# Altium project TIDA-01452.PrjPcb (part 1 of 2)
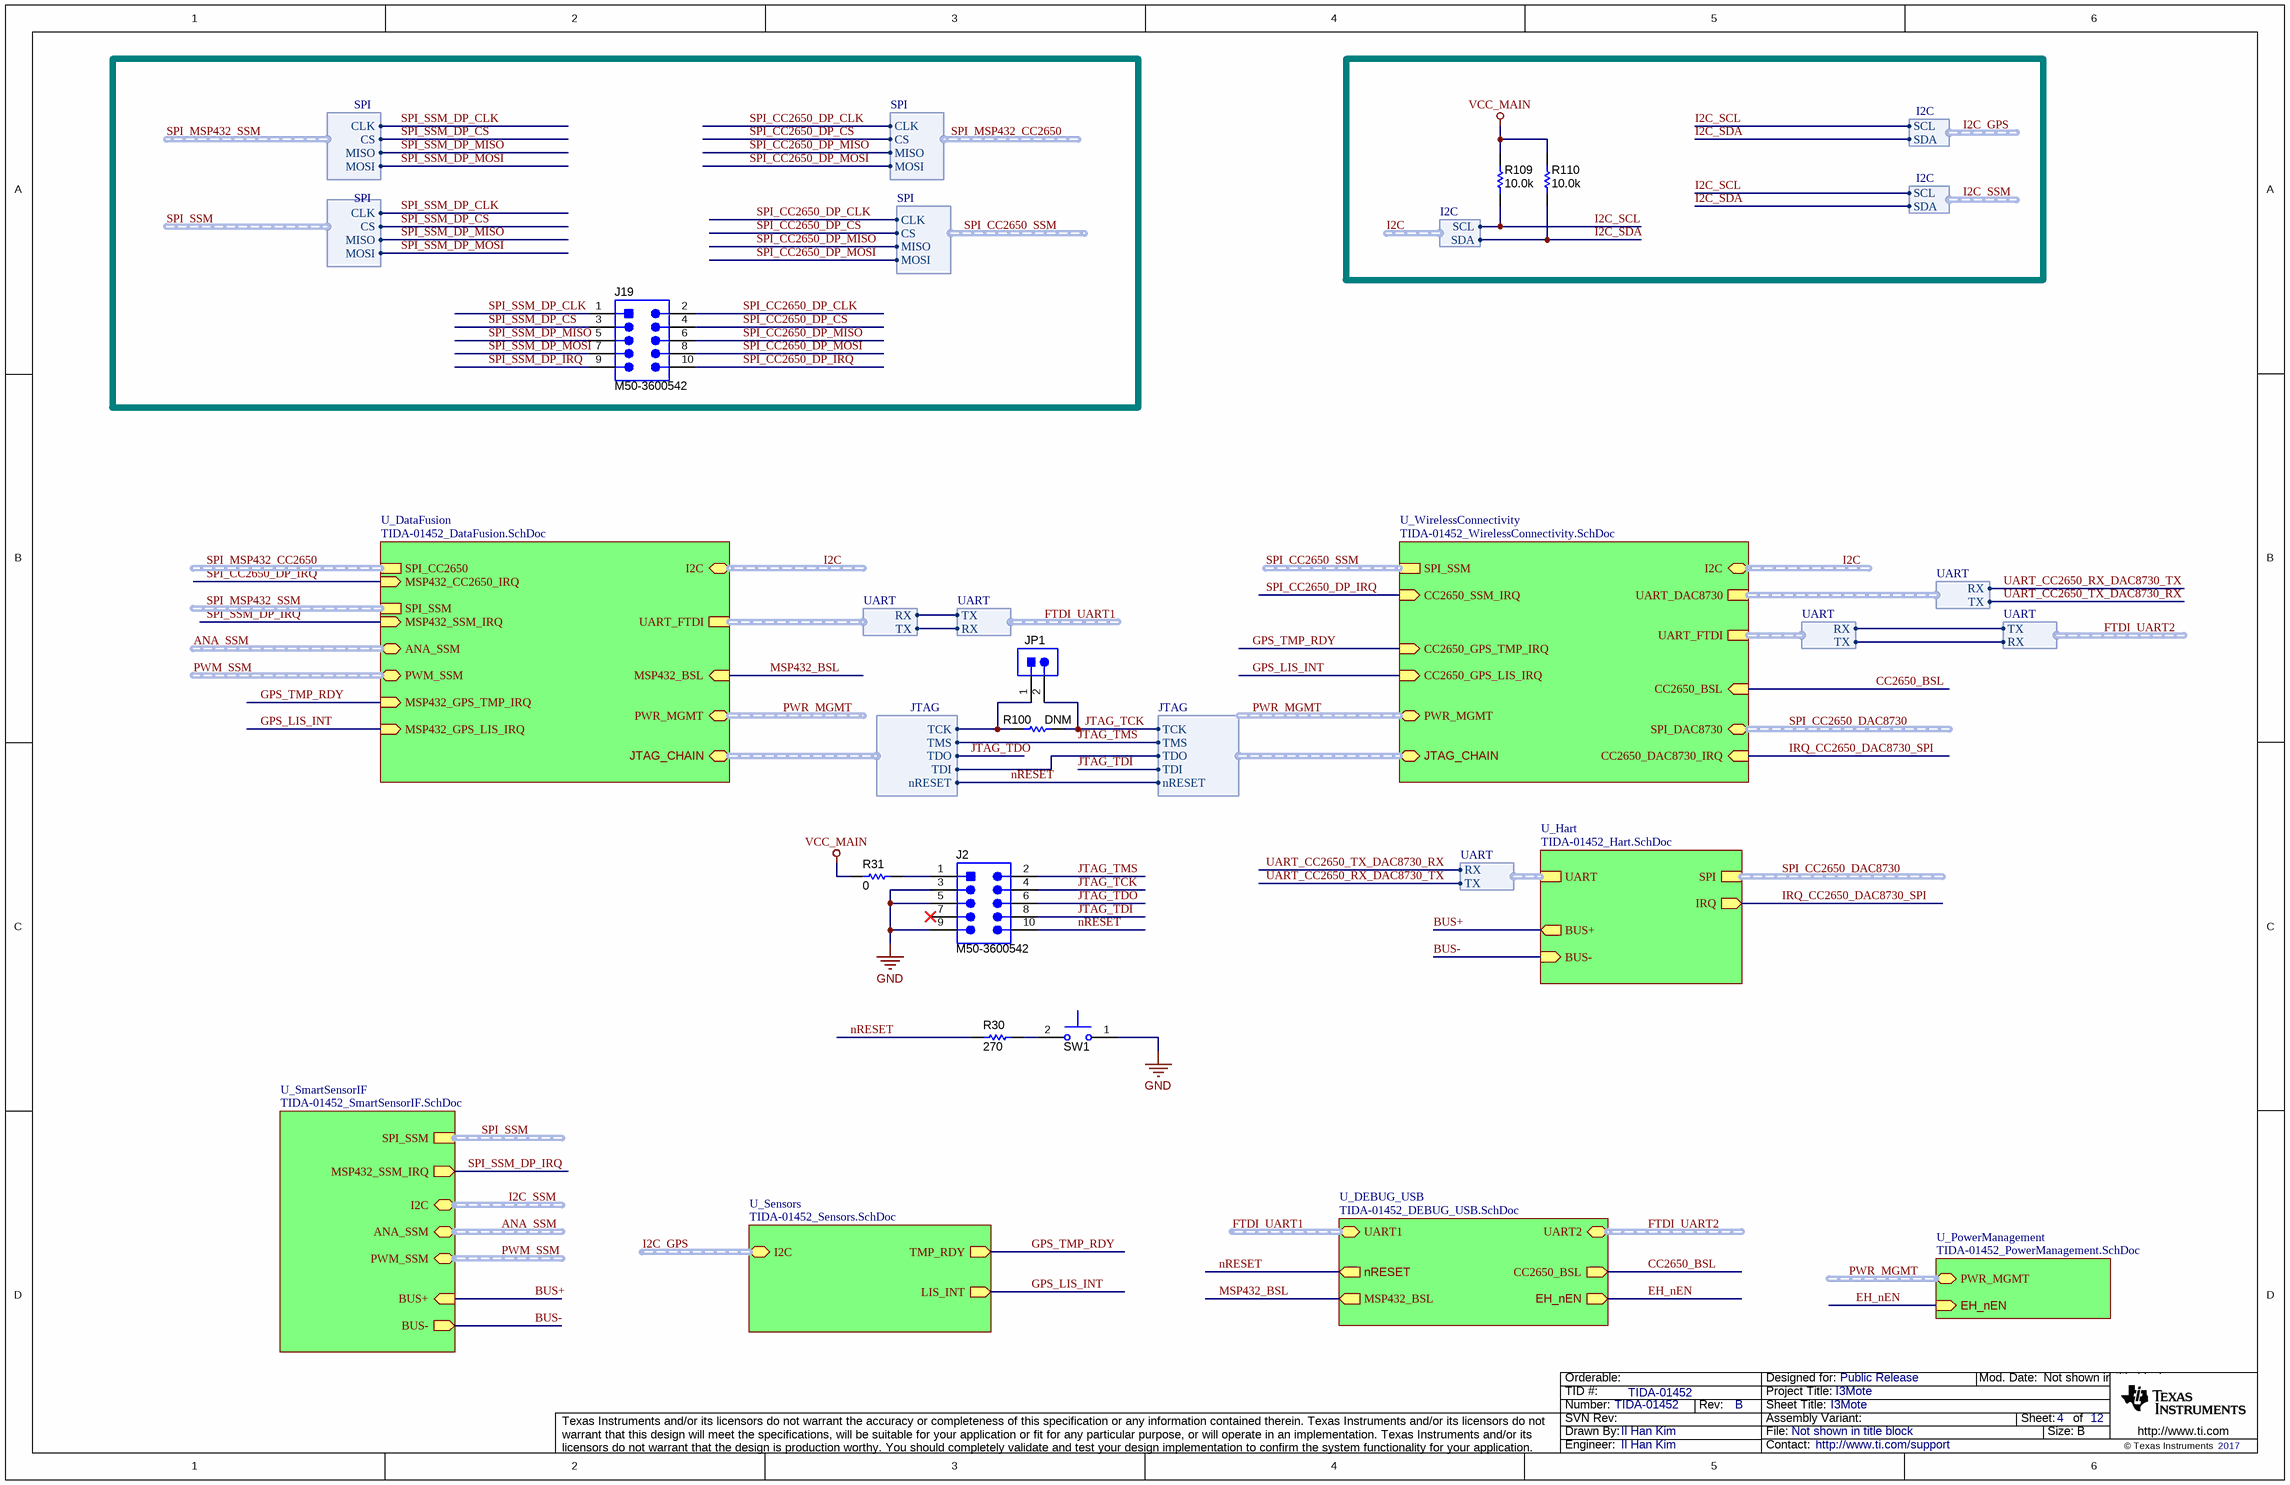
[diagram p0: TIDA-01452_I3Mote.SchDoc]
CopyrightYear: 2017; PCB_Layout: Il Han Kim; PCB_Rev: B; PRJ_Customer: Public Release; PRJ_Engineer: Il Han Kim; PRJ_Number: TIDA-01452; PRJ_Title: I3Mote; SCH_Rev: B; TechSupport: http://www.ti.com/support; TID: TIDA-01452
9 sheets, 257 parts. Net scope: hierarchical (ports join the sheet entries above them; power ports are global).
Board file: TIDA-01452.PcbDoc
Sheets:
  TIDA-01452_I3Mote.SchDoc
    U_Sensors = TIDA-01452_Sensors.SchDoc
    U_PowerManagement = TIDA-01452_PowerManagement.SchDoc
      U_PWR_EH = TIDA-01452_PWR_EH.SchDoc
    U_Hart = TIDA-01452_Hart.SchDoc
    U_DEBUG_USB = TIDA-01452_DEBUG_USB.SchDoc
    U_WirelessConnectivity = TIDA-01452_WirelessConnectivity.SchDoc
    U_DataFusion = TIDA-01452_DataFusion.SchDoc
    U_SmartSensorIF = TIDA-01452_SmartSensorIF.SchDoc

## Sheet TIDA-01452_I3Mote.SchDoc: I3Mote
size 431 x 279 mm; Date: Not shown in title block; ApprovedBy: Not shown in title block; CheckedBy: Not shown in title block; Author: Not shown in title block; CompanyName: Not shown in title block; DrawnBy: Il Han Kim; Engineer: Not shown in title block; Organization: Not shown in title block; Address1: Not shown in title block; Address2: Not shown in title block; Address3: Not shown in title block; Address4: Not shown in title block; DocumentNumber: 7; Revision: Use project parameter SCH_Rev; SheetNumber: 4; SheetTotal: 12; PageSetup: Record=PageOptions¦CenterHorizontal=True¦CenterVertical=True¦PrintScale=0.64¦XCorrection=1.00¦YCorrection=1.00¦PrintKind=0¦BorderSize=5000000¦LeftOffset=0¦BottomOffset=0¦Orientation=2¦PaperLength=1000¦PaperWidth=1000¦Scale=100¦PaperSource=15¦PrintQuality=600¦MediaType=1¦DitherType=10¦PrintScaleMode=1¦PaperKind=Letter

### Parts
J2  M50-3600542  [Harwin_M50-3600542]
J19  M50-3600542  [Harwin_M50-3600542]
JP1  TMM-102-01-T-S  [CONN_TMM-102-01-T-S]  (value not drawn)
R30  ValueDisplayed: 270  [0402]  (hidden comment: CRCW0402270RFKED)
R31  ValueDisplayed: 0  [0402]  (hidden comment: CRCW04020000Z0ED)
R100  DNM  [0402]
R109  ValueDisplayed: 10.0k  [0402]  (hidden comment: CRCW040210K0FKED)
R110  ValueDisplayed: 10.0k  [0402]  (hidden comment: CRCW040210K0FKED)
SW1  B3U-1000P  [SW_B3U-1000P]  (value not drawn)

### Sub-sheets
U_DataFusion = TIDA-01452_DataFusion.SchDoc: UART_FTDI (harness UART), SPI_SSM (harness SPI), SPI_CC2650 (harness SPI), MSP432_GPS_TMP_IRQ (in), MSP432_CC2650_IRQ (in), MSP432_BSL (in), PWR_MGMT (harness PWR_MGMT), MSP432_SSM_IRQ (in), PWM_SSM (harness PWM), ANA_SSM (harness ANA), I2C (harness I2C), JTAG_CHAIN (harness JTAG), MSP432_GPS_LIS_IRQ (in)
U_DEBUG_USB = TIDA-01452_DEBUG_USB.SchDoc: CC2650_BSL (out), MSP432_BSL (out), UART1 (harness UART), UART2 (harness UART), EH_nEN (out), nRESET (out)
U_Hart = TIDA-01452_Hart.SchDoc: SPI (harness SPI), UART (harness UART), IRQ (out), BUS- (in), BUS+ (out)
U_PowerManagement = TIDA-01452_PowerManagement.SchDoc: PWR_MGMT (harness PWR_MGMT), EH_nEN (in)
U_Sensors = TIDA-01452_Sensors.SchDoc: TMP_RDY (out), I2C (harness I2C), LIS_INT (out)
U_SmartSensorIF = TIDA-01452_SmartSensorIF.SchDoc: SPI_SSM (harness SPI), MSP432_SSM_IRQ (out), PWM_SSM (harness PWM), ANA_SSM (harness ANA), I2C (harness I2C), BUS- (out), BUS+ (in)
U_WirelessConnectivity = TIDA-01452_WirelessConnectivity.SchDoc: SPI_SSM (harness SPI), UART_DAC8730 (harness UART), UART_FTDI (harness UART), CC2650_SSM_IRQ (in), CC2650_GPS_TMP_IRQ (in), CC2650_BSL (in), PWR_MGMT (harness PWR_MGMT), CC2650_DAC8730_IRQ (in), SPI_DAC8730 (harness SPI), I2C (harness I2C), JTAG_CHAIN (harness JTAG), CC2650_GPS_LIS_IRQ (in)

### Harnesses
UART: RX, TX
I2C: SCL, SDA
SPI: CLK, CS, MISO, MOSI
JTAG: TMS, TCK, TDO, TDI, nRESET

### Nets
GND: J2.3 J2.5 J2.9 SW1.1
VCC_MAIN: R31.1 R109.1 R110.1
BUS+: sheet U_Hart/BUS+, sheet U_SmartSensorIF/BUS+
BUS-: sheet U_Hart/BUS-, sheet U_SmartSensorIF/BUS-
CC2650_BSL: sheet U_DEBUG_USB/CC2650_BSL, sheet U_WirelessConnectivity/CC2650_BSL
CC2650_FTDI_UART_RX: sheet U_WirelessConnectivity/UART_FTDI.RX, sheet U_DEBUG_USB/UART2.TX
CC2650_FTDI_UART_TX: sheet U_WirelessConnectivity/UART_FTDI.TX, sheet U_DEBUG_USB/UART2.RX
CC2650_JTAG_TDO: sheet U_DataFusion/JTAG_CHAIN.TDI, sheet U_WirelessConnectivity/JTAG_CHAIN.TDO
EH_nEN: sheet U_PowerManagement/EH_nEN, sheet U_DEBUG_USB/EH_nEN
FTDI_UART1.RX: sheet U_DataFusion/UART_FTDI.TX, sheet U_DEBUG_USB/UART1.RX
FTDI_UART1.TX: sheet U_DataFusion/UART_FTDI.RX, sheet U_DEBUG_USB/UART1.TX
GPS_LIS_INT: sheet U_Sensors/LIS_INT, sheet U_WirelessConnectivity/CC2650_GPS_LIS_IRQ, sheet U_DataFusion/MSP432_GPS_LIS_IRQ  [project net CC2650_GPS_LIS_IRQ]
GPS_TMP_RDY: sheet U_Sensors/TMP_RDY, sheet U_WirelessConnectivity/CC2650_GPS_TMP_IRQ, sheet U_DataFusion/MSP432_GPS_TMP_IRQ  [project net CC2650_GPS_TMP_IRQ]
I2C_SCL: R109.2 ; sheet U_WirelessConnectivity/I2C.SCL, sheet U_Sensors/I2C.SCL, sheet U_SmartSensorIF/I2C.SCL  [project net CC2650_GPS_I2C_SCL]
I2C_SDA: R110.2 ; sheet U_WirelessConnectivity/I2C.SDA, sheet U_Sensors/I2C.SDA, sheet U_SmartSensorIF/I2C.SDA  [project net CC2650_GPS_I2C_SDA]
IRQ_CC2650_DAC8730_SPI: sheet U_Hart/IRQ, sheet U_WirelessConnectivity/CC2650_DAC8730_IRQ  [project net CC2650_DAC8730_IRQ]
JTAG_TCK: J2.4 JP1.2 R100.2 ; sheet U_WirelessConnectivity/JTAG_CHAIN.TCK  [project net CC2650_JTAG_TCK]
JTAG_TDI: J2.8 ; sheet U_WirelessConnectivity/JTAG_CHAIN.TDI  [project net CC2650_JTAG_TDI]
JTAG_TDO: J2.6 ; sheet U_DataFusion/JTAG_CHAIN.TDO
JTAG_TMS: J2.2 ; sheet U_DataFusion/JTAG_CHAIN.TMS, sheet U_WirelessConnectivity/JTAG_CHAIN.TMS  [project net CC2650_JTAG_TMS]
MSP432_BSL: sheet U_DEBUG_USB/MSP432_BSL, sheet U_DataFusion/MSP432_BSL
MSP432_JTAG_TCK: JP1.1 R100.1 ; sheet U_DataFusion/JTAG_CHAIN.TCK
nRESET: J2.10 R30.1 ; sheet U_DEBUG_USB/nRESET, sheet U_DataFusion/JTAG_CHAIN.nRESET, sheet U_WirelessConnectivity/JTAG_CHAIN.nRESET  [project net CC2650_nRESET]
SPI_CC2650_DP_CLK: J19.2 ; sheet U_DataFusion/SPI_CC2650.CLK, sheet U_WirelessConnectivity/SPI_SSM.CLK  [project net CC2650_SSM_SPI_CLK]
SPI_CC2650_DP_CS: J19.4 ; sheet U_DataFusion/SPI_CC2650.CS, sheet U_WirelessConnectivity/SPI_SSM.CS  [project net CC2650_SSM_SPI_CS]
SPI_CC2650_DP_IRQ: J19.10 ; sheet U_WirelessConnectivity/CC2650_SSM_IRQ, sheet U_DataFusion/MSP432_CC2650_IRQ  [project net CC2650_SSM_IRQ]
SPI_CC2650_DP_MISO: J19.6 ; sheet U_DataFusion/SPI_CC2650.MISO, sheet U_WirelessConnectivity/SPI_SSM.MISO  [project net CC2650_SSM_SPI_MISO]
SPI_CC2650_DP_MOSI: J19.8 ; sheet U_DataFusion/SPI_CC2650.MOSI, sheet U_WirelessConnectivity/SPI_SSM.MOSI  [project net CC2650_SSM_SPI_MOSI]
SPI_SSM_DP_CLK: J19.1 ; sheet U_DataFusion/SPI_SSM.CLK, sheet U_SmartSensorIF/SPI_SSM.CLK  [project net MSP432_SSM_SPI_CLK]
SPI_SSM_DP_CS: J19.3 ; sheet U_DataFusion/SPI_SSM.CS, sheet U_SmartSensorIF/SPI_SSM.CS  [project net MSP432_SSM_SPI_CS]
SPI_SSM_DP_IRQ: J19.9 ; sheet U_DataFusion/MSP432_SSM_IRQ, sheet U_SmartSensorIF/MSP432_SSM_IRQ  [project net IRQ_MSP432_SSM]
SPI_SSM_DP_MISO: J19.5 ; sheet U_DataFusion/SPI_SSM.MISO, sheet U_SmartSensorIF/SPI_SSM.MISO  [project net MSP432_SSM_SPI_MISO]
SPI_SSM_DP_MOSI: J19.7 ; sheet U_DataFusion/SPI_SSM.MOSI, sheet U_SmartSensorIF/SPI_SSM.MOSI  [project net MSP432_SSM_SPI_MOSI]
UART_CC2650_RX_DAC8730_TX: sheet U_Hart/UART.TX, sheet U_WirelessConnectivity/UART_DAC8730.RX  [project net CC2650_DAC8730_UART_RX]
UART_CC2650_TX_DAC8730_RX: sheet U_Hart/UART.RX, sheet U_WirelessConnectivity/UART_DAC8730.TX  [project net CC2650_DAC8730_UART_TX]
NetJ2_1: J2.1 R31.2
NetR30_2: R30.2 SW1.2

Not connected (* = marked no-connect by the designer): J2 7*

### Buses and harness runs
harness ANA_SSM = sheet U_DataFusion/ANA_SSM
harness ANA_SSM = sheet U_SmartSensorIF/ANA_SSM
harness FTDI_UART1 = sheet U_DEBUG_USB/UART1
harness FTDI_UART2 = sheet U_DEBUG_USB/UART2
harness I2C = sheet U_DataFusion/I2C
harness I2C = sheet U_WirelessConnectivity/I2C
harness I2C_GPS = sheet U_Sensors/I2C
harness I2C_SSM = sheet U_SmartSensorIF/I2C
harness PWM_SSM = sheet U_DataFusion/PWM_SSM
harness PWM_SSM = sheet U_SmartSensorIF/PWM_SSM
harness PWR_MGMT = sheet U_DataFusion/PWR_MGMT
harness PWR_MGMT = sheet U_PowerManagement/PWR_MGMT
harness PWR_MGMT = sheet U_WirelessConnectivity/PWR_MGMT
harness SPI_CC2650_DAC8730 = sheet U_Hart/SPI
harness SPI_CC2650_DAC8730 = sheet U_WirelessConnectivity/SPI_DAC8730
harness SPI_CC2650_SSM = sheet U_WirelessConnectivity/SPI_SSM
harness SPI_MSP432_CC2650 = sheet U_DataFusion/SPI_CC2650
harness SPI_MSP432_SSM = sheet U_DataFusion/SPI_SSM
harness SPI_SSM = sheet U_SmartSensorIF/SPI_SSM

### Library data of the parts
J2 J19 = M50-3600542: Header, 1.27mm, 5x2, Gold, SMT; Manufacturer: Harwin; SymbolCreator: a0412235; Pitch_mm: 1.27; Gender: Male; Shrouded: N; Row_Count: 2; Current_A: 1; Voltage_V: 1000; Cert_UL: Y
JP1 = TMM-102-01-T-S: Header, 2mm, 2x1, Tin, TH; Manufacturer: Samtec; SymbolCreator: a0412235; U/M: EA
R30 = CRCW0402270RFKED: RES, 270, 1%, 0.0625W, 50V, 0402; Manufacturer: Vishay-Dale; Value: 270
R31 R100 = CRCW04020000Z0ED: RES, 0, 5%, 0.063 W, 0402; Manufacturer: Vishay-Dale; CompType: Resistor; Value: 0; Value_Code: 0000; Tolerance_%: 5; Power_W: 0.063; Value2: 0.063W; VDC_V: 50; TempCo: 200 ppm/C; EIA_Code: E24; U/M: EA
R109 R110 = CRCW040210K0FKED: RES, 10.0 k, 1%, 0.063 W, 0402; Manufacturer: Vishay-Dale; CompType: Resistor; Value: 10.0k; Res_ohm: 10000; Value_Code: 10k0; Tolerance_%: 1; Power_W: 0.063; Value2: 0.063W; VDC_V: 50; TempCo: 100 ppm/C; EIA_Code: E96; U/M: EA; AEC Category: Q200
SW1 = B3U-1000P: SWITCH TACTILE SPST-NO 0.05A 12V; Manufacturer: Omron Electronic Components; SymbolCreator: a0412235; VDC_V: 12; SwitchFunction: Off-Mom; PositionCount: 1; CurrentRating_mA: 50

## Sheet TIDA-01452_Sensors.SchDoc: Sensors
size 431 x 279 mm; Date: Not shown in title block; ApprovedBy: Not shown in title block; CheckedBy: Not shown in title block; Author: Not shown in title block; CompanyName: Not shown in title block; DrawnBy: Il Han Kim; Engineer: Not shown in title block; Organization: Not shown in title block; Address1: Not shown in title block; Address2: Not shown in title block; Address3: Not shown in title block; Address4: Not shown in title block; DocumentNumber: 10; Revision: Use project parameter SCH_Rev; SheetNumber: 6; SheetTotal: 12; PageSetup: Record=PageOptions¦CenterHorizontal=True¦CenterVertical=True¦PrintScale=1.00¦XCorrection=1.00¦YCorrection=1.00¦PrintKind=0¦BorderSize=5000000¦LeftOffset=0¦BottomOffset=0¦Orientation=2¦PaperLength=1000¦PaperWidth=1000¦Scale=100¦PaperSource=15¦PrintQuality=600¦MediaType=1¦DitherType=10¦PaperKind=Letter¦PrintScaleMode=1
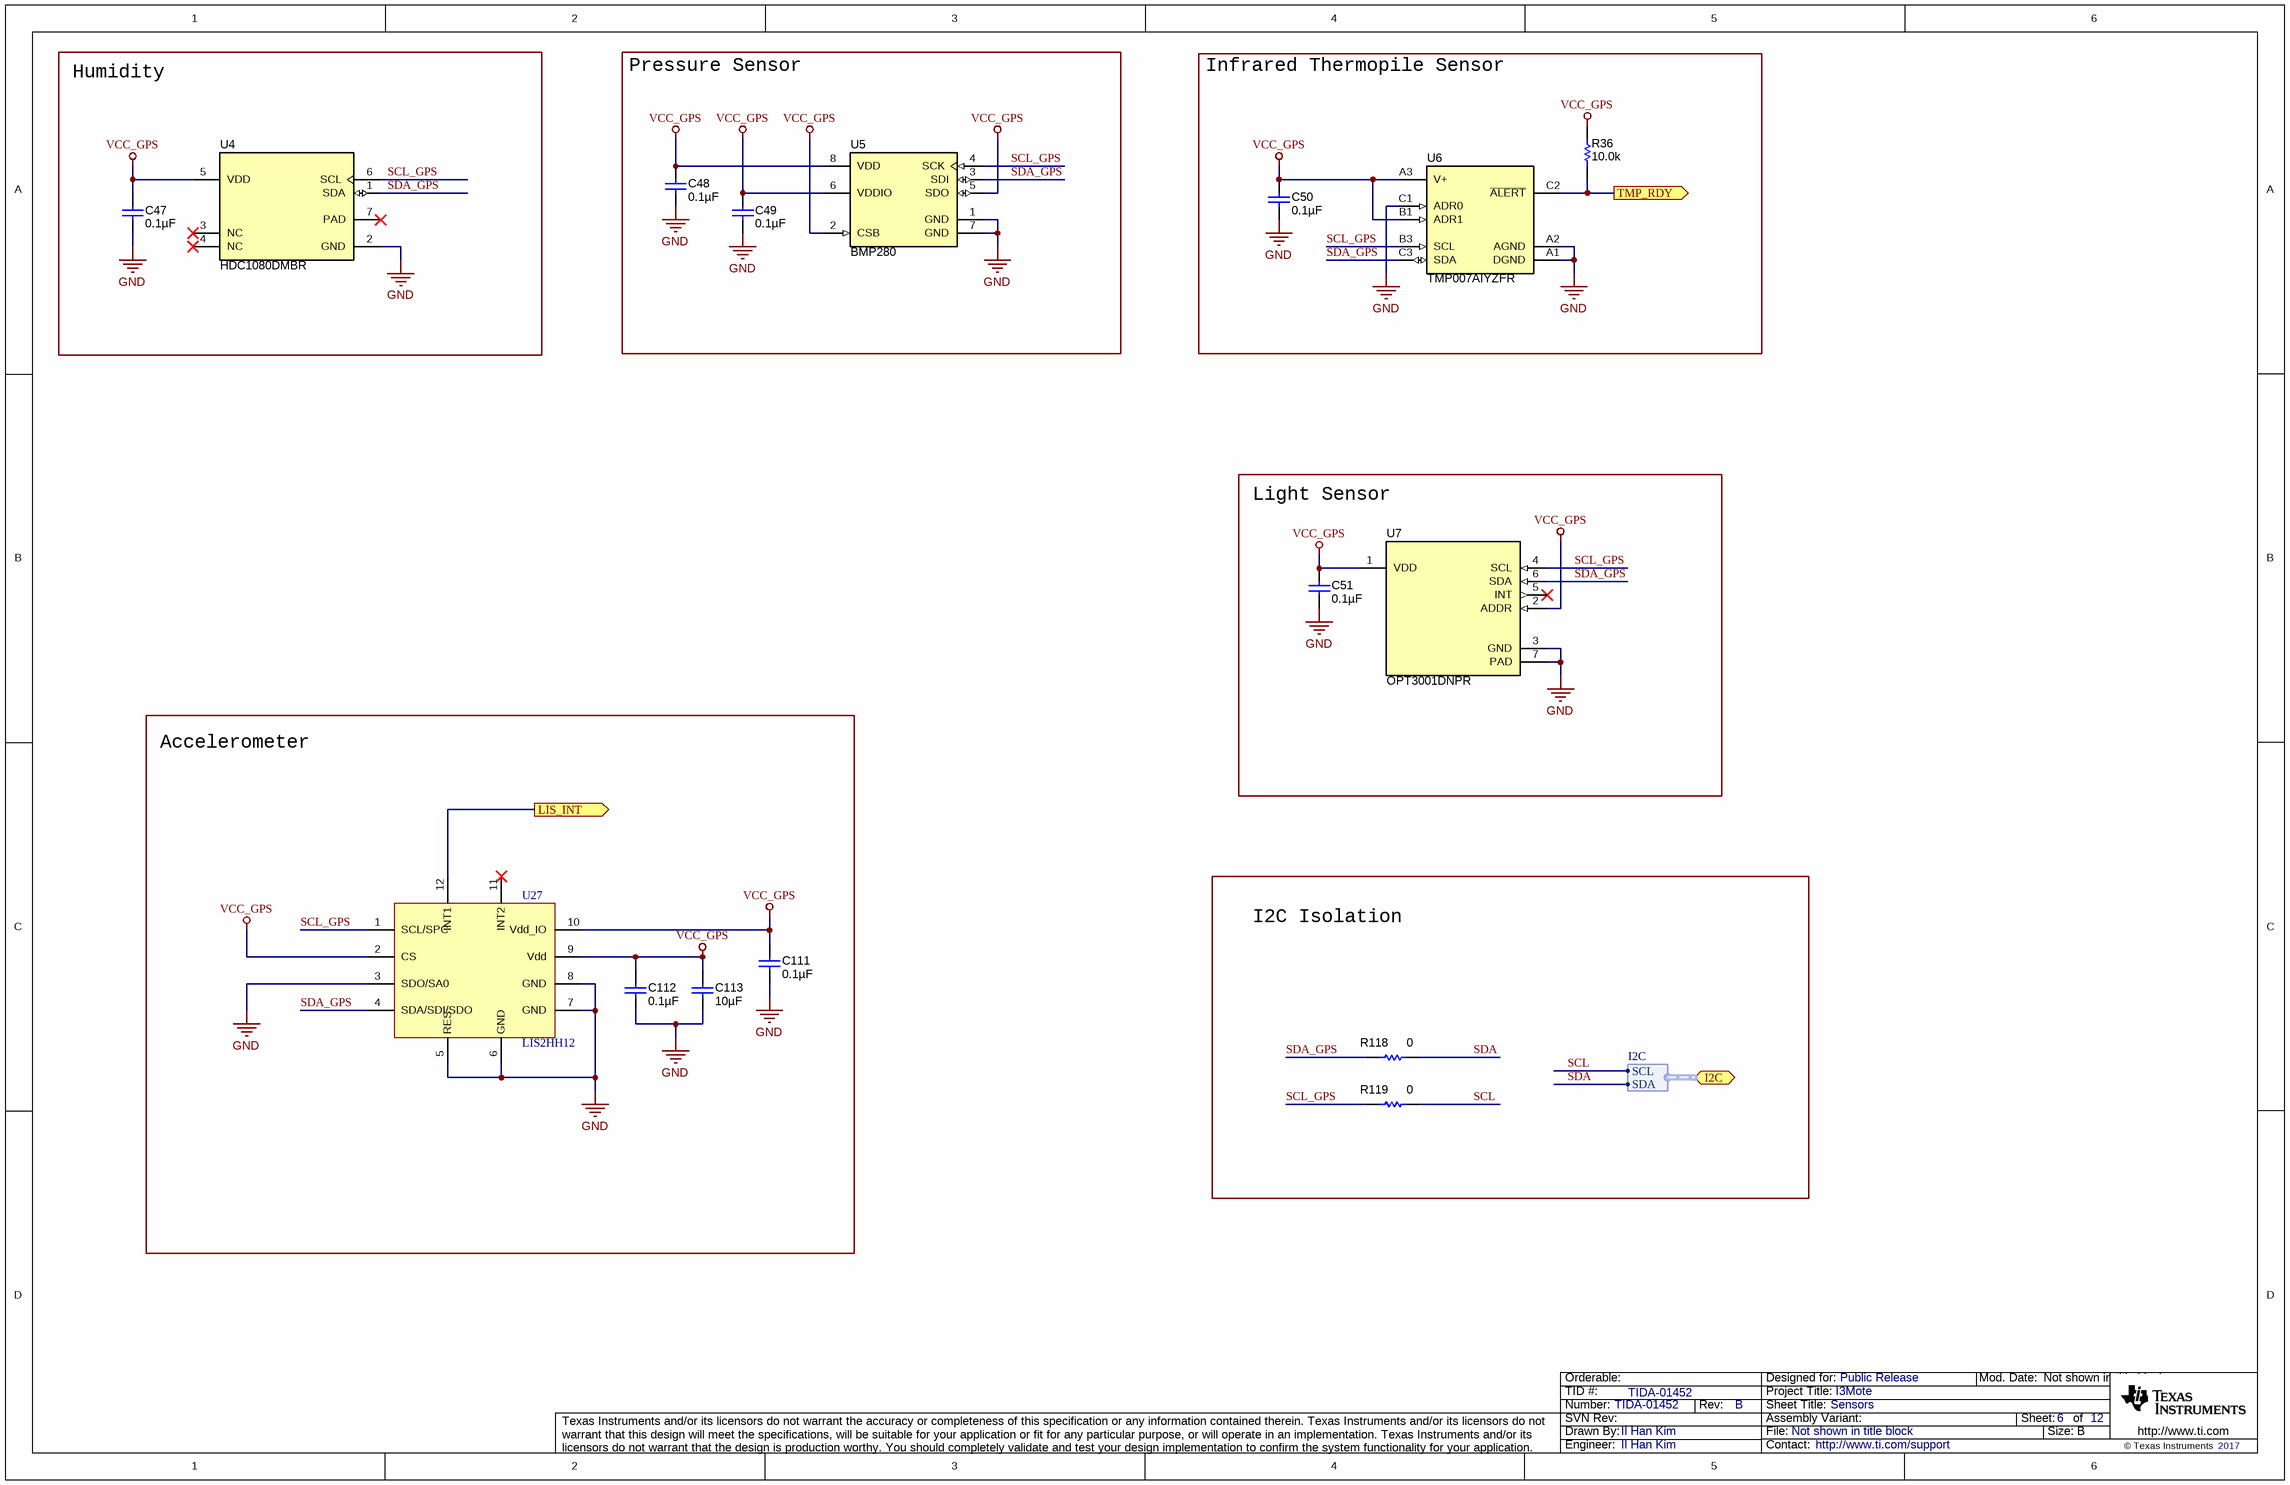
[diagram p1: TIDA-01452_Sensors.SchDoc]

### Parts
C47  ValueDisplayed: 0.1µF  [0402]  (hidden comment: GCM155R71H104KE02D)
C48  ValueDisplayed: 0.1µF  [0402]  (hidden comment: GCM155R71H104KE02D)
C49  ValueDisplayed: 0.1µF  [0402]  (hidden comment: GCM155R71H104KE02D)
C50  ValueDisplayed: 0.1µF  [0402]  (hidden comment: GCM155R71H104KE02D)
C51  ValueDisplayed: 0.1µF  [0402]  (hidden comment: GCM155R71H104KE02D)
C111  ValueDisplayed: 0.1µF  [0402]  (hidden comment: GCM155R71H104KE02D)
C112  ValueDisplayed: 0.1µF  [0402]  (hidden comment: GCM155R71H104KE02D)
C113  ValueDisplayed: 10µF  [0603]  (hidden comment: GRM188R60J106ME47D)
R36  ValueDisplayed: 10.0k  [0402]  (hidden comment: CRCW040210K0FKED)
R118  ValueDisplayed: 0  [0402]  (hidden comment: CRCW04020000Z0ED)
R119  ValueDisplayed: 0  [0402]  (hidden comment: CRCW04020000Z0ED)
U4  HDC1080DMBR  [DMB0006A]
U5  BMP280  [LGA8-2X2_5MM_0_65]
U6  TMP007AIYZFR  [YZF0008AEAE]
U7  OPT3001DNPR  [DNP0006A]
U27  LIS2HH12  [LGA12-2X2MM_0_50]

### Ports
I2C (harness I2C), LIS_INT (out), TMP_RDY (out)

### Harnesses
I2C: SCL, SDA

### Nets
GND: C47.2 C48.2 C49.2 C50.2 C51.2 C111.2 C112.2 C113.2 U4.2(GND) U5.1(GND) U5.7(GND) U6.A1(DGND) U6.A2(AGND) U6.C1(ADR0) U7.3(GND) U7.7(PAD) U27.3(SDO/SA0) U27.5(RES) U27.6(GND) U27.7(GND) U27.8(GND)
VCC_GPS: C47.1 C48.1 C49.1 C50.1 C51.1 C111.1 C112.1 C113.1 R36.1 U4.5(VDD) U5.2(CSB) U5.5(SDO) U5.6(VDDIO) U5.8(VDD) U6.A3(V+) U6.B1(ADR1) U7.1(VDD) U7.2(ADDR) U27.2(CS) U27.9(Vdd) U27.10(Vdd_IO)
CC2650_GPS_LIS_IRQ: U27.12(INT1) ; port LIS_INT
CC2650_GPS_TMP_IRQ: R36.2 U6.C2(~{ALERT}) ; port TMP_RDY
SCL: R119.1 ; port I2C.SCL  [project net CC2650_GPS_I2C_SCL]
SCL_GPS: R119.2 U4.6(SCL) U5.4(SCK) U6.B3(SCL) U7.4(SCL) U27.1(SCL/SPC)
SDA: R118.1 ; port I2C.SDA  [project net CC2650_GPS_I2C_SDA]
SDA_GPS: R118.2 U4.1(SDA) U5.3(SDI) U6.C3(SDA) U7.6(SDA) U27.4(SDA/SDI/SDO)

Not connected (* = marked no-connect by the designer): U4 3(NC)* 4(NC)* 7(PAD)*; U7 5(INT)*; U27 11(INT2)*

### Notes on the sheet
- Humidity
- Pressure Sensor
- Infrared Thermopile Sensor
- Light Sensor
- Accelerometer
- I2C Isolation

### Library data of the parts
C47-C51 C111 C112 = GCM155R71H104KE02D: CAP, CERM, 0.1 µF, 50 V, +/- 10%, X7R, AEC-Q200 Grade 1, 0402; Manufacturer: MuRata; Polarized: N; CompType: Capacitor; Value: 0.1uF; U/M: EA; Cap_F: 0.0000001; Tolerance_%: 10; Value1: Unknown; VDC_V: 50; Value2: 50V; TaMin_C: -55; TaMax_C: 125; AEC Category: Q200; AEC Qualified: Y; AEC Grade: 1
C113 = GRM188R60J106ME47D: CAP, CERM, 10 µF, 6.3 V, +/- 20%, X5R, 0603; Manufacturer: MuRata; Polarized: N; CompType: Capacitor; Value: 10uF; U/M: EA; Cap_F: 0.00001; Tolerance_%: 20; ESR_ohm: 0.009; Value1: 0.009 ohm; VDC_V: 6.3; Value2: 6.3V; IRMS_A: 2.74; TaMin_C: -55; TaMax_C: 125; SizeArea_mm2: 1.28; SizeAreaWB_mm2: 4.68; SizeX_mm: 1.6; SizeY_mm: 0.8; SizeZ_mm: 1; AEC Category: Q200
R36 = CRCW040210K0FKED: as R109 on sheet TIDA-01452_I3Mote
R118 R119 = CRCW04020000Z0ED: RES, 0, 5%, 0.063 W, 0402; Manufacturer: Vishay-Dale; CompType: Resistor; Value: 0; Value_Code: 0000; Tolerance_%: 5; Power_W: 0.063; Value2: 0.063W; VDC_V: 50; TempCo: 200 ppm/C; EIA_Code: E24; U/M: EA; AEC Category: Q200
U4 = HDC1080DMBR: Low Power, High Accuracy Digital Humidity Sensor with Temperature Sensor, DMB0006A; Alternate PartNumber: HDC1080DMBT; Manufacturer: Texas Instruments; SymbolCreator: a0411947; SizeArea_mm2: 9; SizeAreaWB_mm2: 16; SizeX_mm: 3; SizeZ_mm: 0.8; CompType: IC; U/M: EA
U5 = BMP280: Digital Pressure Sensor, LGA8-2X2_5MM_0_65; Manufacturer: Bosch Solar Energy; SymbolCreator: Altium
U6 = TMP007AIYZFR: Infrared Thermopile Sensor with Integrated Math Engine, YZF0008AEAE; Alternate PartNumber: TMP007AIYZFT; Manufacturer: Texas Instruments; SymbolCreator: a0411947; SizeArea_mm2: 2.359296; SizeX_mm: 1.536; SizeZ_mm: 0.625; CompType: IC; U/M: EA
U7 = OPT3001DNPR: Ambient Light Sensor, DNP0006A; Alternate PartNumber: OPT3001DNPT; Manufacturer: Texas Instruments; SymbolCreator: a0411947; SizeArea_mm2: 4; SizeX_mm: 2; SizeZ_mm: 0.65; CompType: IC; U/M: EA
U27 = LIS2HH12: Ultra-low-power high-performance 3-axis pico accelerometer; Manufacturer: ST Microelectronics

## Sheet TIDA-01452_PowerManagement.SchDoc: PowerManagement
size 431 x 279 mm; Date: Not shown in title block; ApprovedBy: Not shown in title block; CheckedBy: Not shown in title block; Author: Not shown in title block; CompanyName: Not shown in title block; DrawnBy: Il Han Kim; Engineer: Not shown in title block; Organization: Not shown in title block; Address1: Not shown in title block; Address2: Not shown in title block; Address3: Not shown in title block; Address4: Not shown in title block; DocumentNumber: 8; Revision: Use project parameter SCH_Rev; SheetNumber: 9; SheetTotal: 12; PageSetup: Record=PageOptions¦CenterHorizontal=True¦CenterVertical=True¦PrintScale=1.00¦XCorrection=1.00¦YCorrection=1.00¦PrintKind=0¦BorderSize=5000000¦LeftOffset=0¦BottomOffset=0¦Orientation=2¦PaperLength=1000¦PaperWidth=1000¦Scale=100¦PaperSource=15¦PrintQuality=600¦MediaType=1¦DitherType=10¦PaperKind=Letter¦PrintScaleMode=1
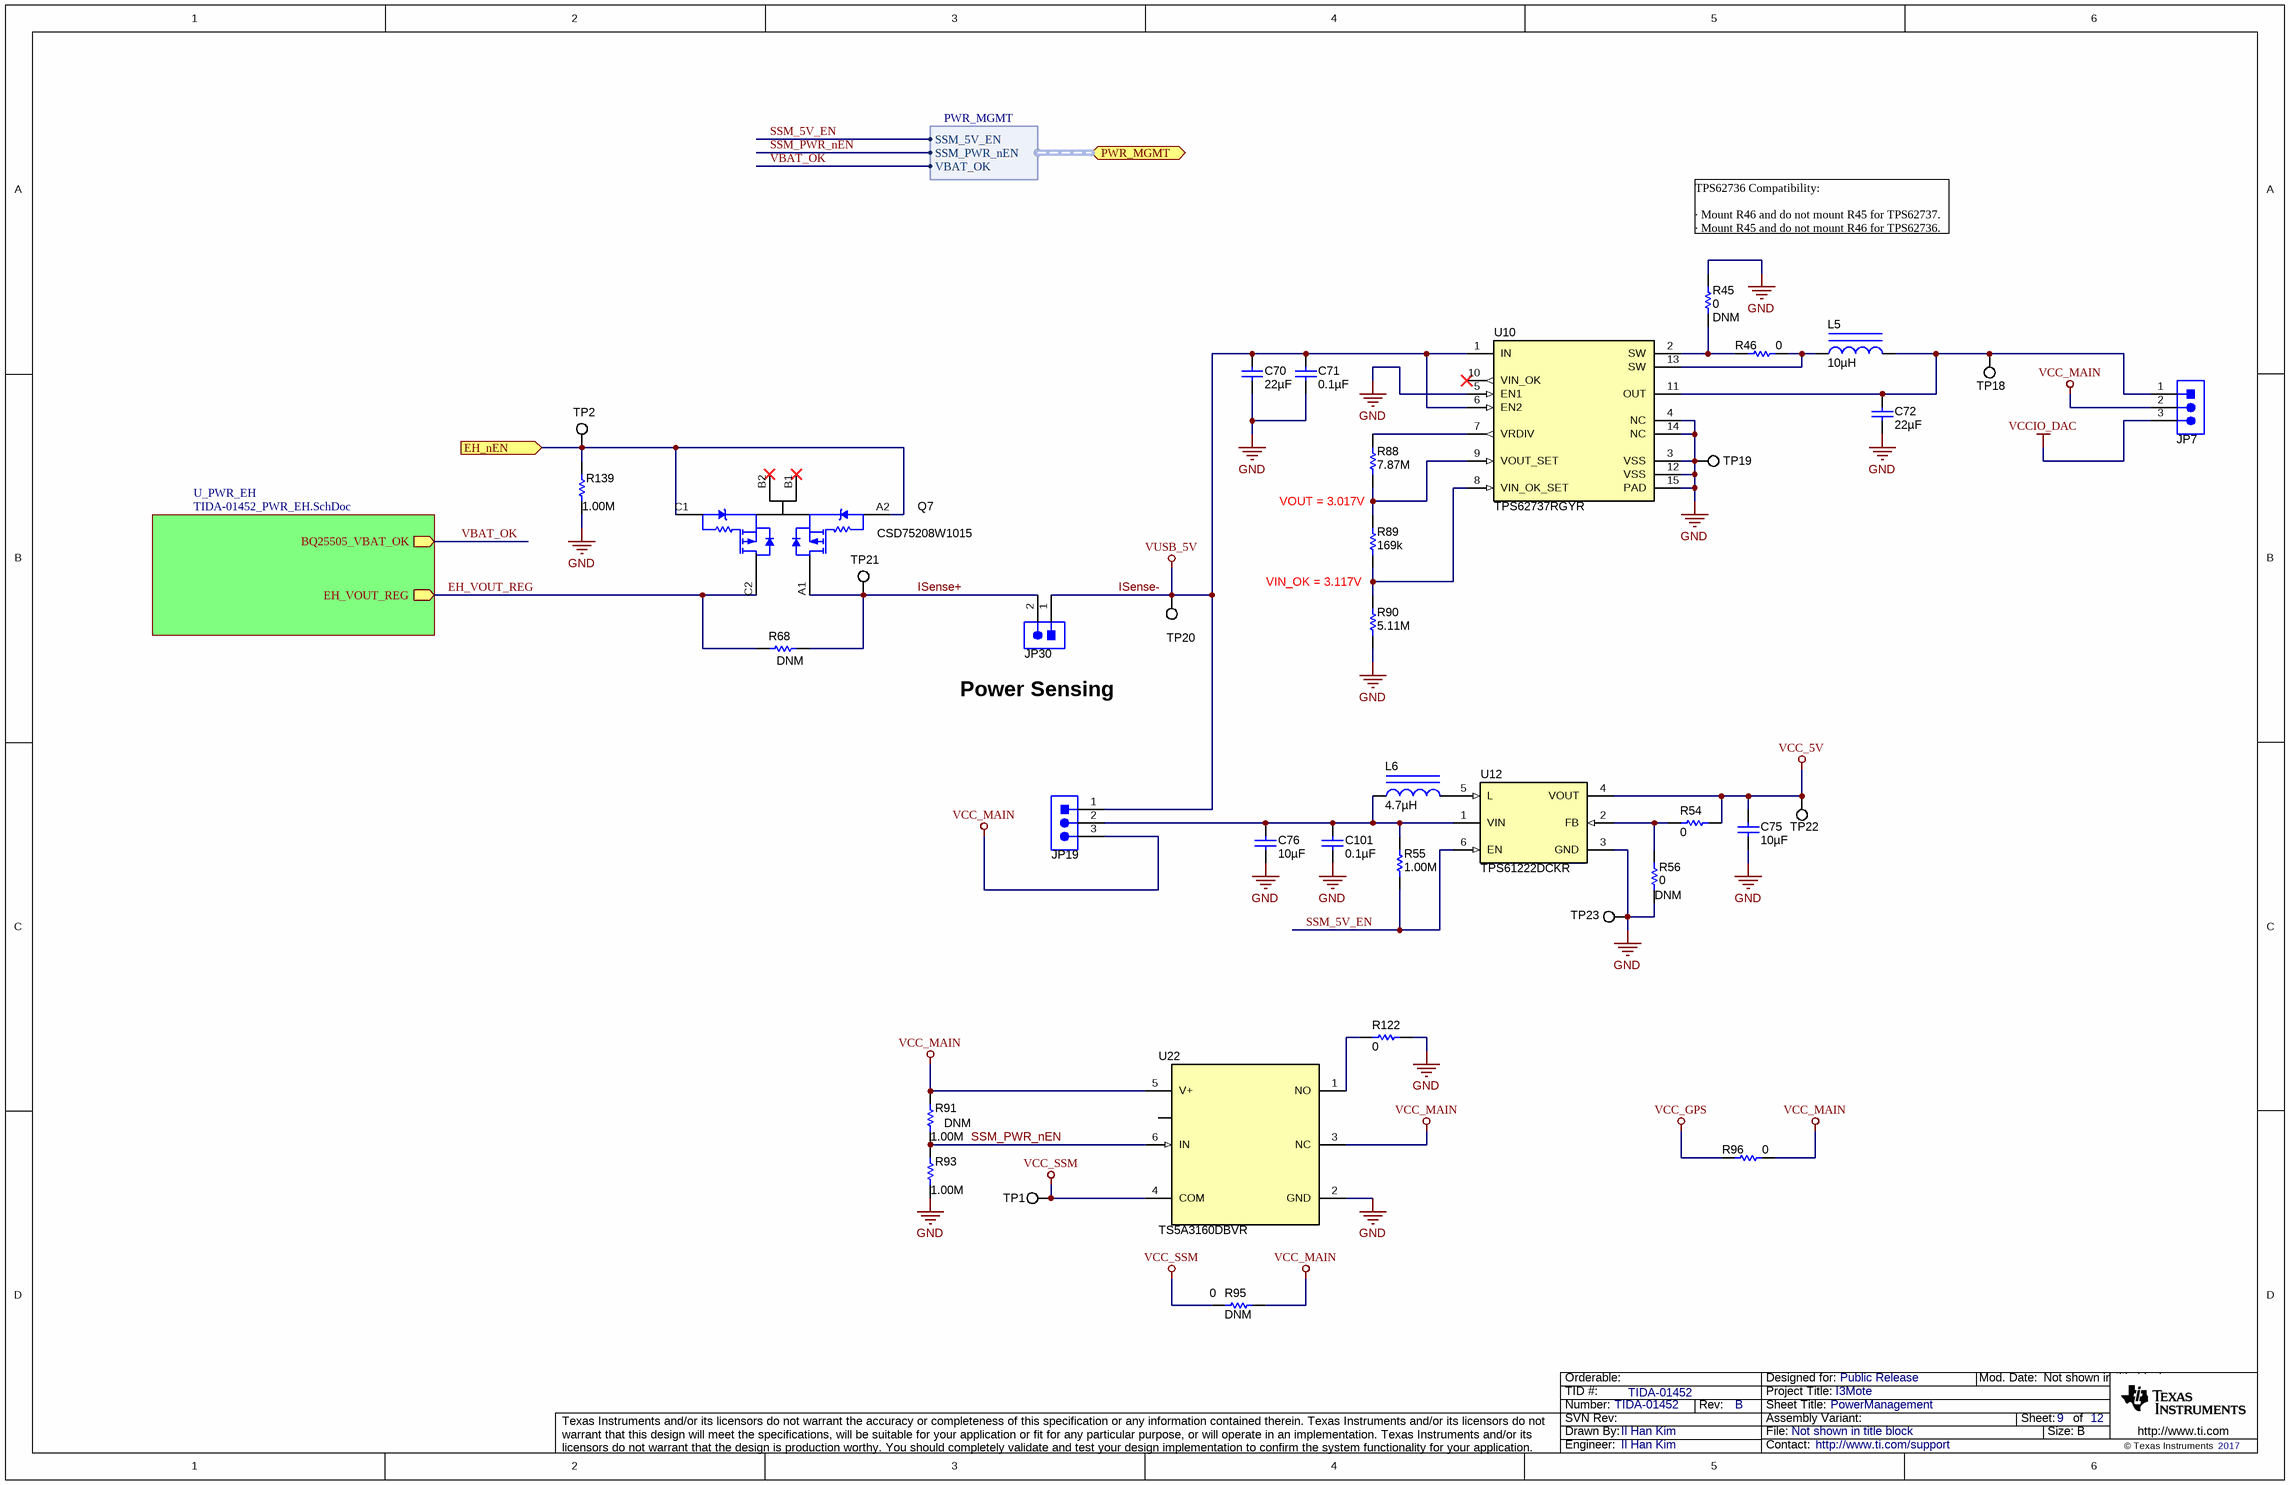
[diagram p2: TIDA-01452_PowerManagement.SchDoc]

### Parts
C70  ValueDisplayed: 22µF  [0603]  (hidden comment: GRM188R61A226ME15D)
C71  ValueDisplayed: 0.1µF  [0402]  (hidden comment: GRM155R70J104KA01D)
C72  ValueDisplayed: 22µF  [0603]  (hidden comment: GRM188R61A226ME15D)
C75  ValueDisplayed: 10µF  [0603]  (hidden comment: GRM188R60J106ME47D)
C76  ValueDisplayed: 10µF  [0603]  (hidden comment: GRM188R60J106ME47D)
C101  ValueDisplayed: 0.1µF  [0402]  (hidden comment: GRM155R70J104KA01D)
JP7  TMM-103-01-T-S  [CONN_TMM-103-01-T-S]  (value not drawn)
JP19  TMM-103-01-T-S  [CONN_TMM-103-01-T-S]  (value not drawn)
JP30  TMM-102-01-T-S  [CONN_TMM-102-01-T-S]  (value not drawn)
L5  ValueDisplayed: 10µH  [LPS4018]  (hidden comment: LPS4018-103MLB)
L6  ValueDisplayed: 4.7µH  [EPL3015]  (hidden comment: EPL3015-472MLB)
Q7  CSD75208W1015  [YZC0006ABBB]
R45  DNM  ValueDisplayed: 0  [0402]
R46  ValueDisplayed: 0  [0402]  (hidden comment: CRCW04020000Z0ED)
R54  ValueDisplayed: 0  [0402]  (hidden comment: CRCW04020000Z0ED)
R55  ValueDisplayed: 1.00M  [0402]  (hidden comment: CRCW04021M00FKED)
R56  DNM  ValueDisplayed: 0  [0402]
R68  DNM  [0402]
R88  ValueDisplayed: 7.87M  [0402]  (hidden comment: CRCW04027M87FKED)
R89  ValueDisplayed: 169k  [0402]  (hidden comment: CRCW0402169KFKED)
R90  ValueDisplayed: 5.11M  [0402]  (hidden comment: CRCW04025M11FKED)
R91  DNM  ValueDisplayed: 1.00M  [0402]
R93  ValueDisplayed: 1.00M  [0402]  (hidden comment: CRCW04021M00FKED)
R95  DNM  ValueDisplayed: 0  [0402]
R96  ValueDisplayed: 0  [0402]  (hidden comment: CRCW04020000Z0ED)
R122  ValueDisplayed: 0  [0402]  (hidden comment: CRCW04020000Z0ED)
R139  ValueDisplayed: 1.00M  [0402]  (hidden comment: CRCW04021M00FKED)
TP1  NA  [TPS0.8]  (value not drawn)  (no BOM)
TP2  NA  [TPS0.8]  (value not drawn)  (no BOM)
TP18  NA  [TPS0.8]  (value not drawn)  (no BOM)
TP19  NA  [TPS0.8]  (value not drawn)  (no BOM)
TP20  NA  [TPS0.8]  (value not drawn)  (no BOM)
TP21  NA  [TPS0.8]  (value not drawn)  (no BOM)
TP22  NA  [TPS0.8]  (value not drawn)  (no BOM)
TP23  NA  [TPS0.8]  (value not drawn)  (no BOM)
U10  TPS62737RGYR  [RGY0014A]
U12  TPS61222DCKR  [DCK0006A_N]
U22  TS5A3160DBVR  [DBV0006A_N]

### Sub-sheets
U_PWR_EH = TIDA-01452_PWR_EH.SchDoc: EH_VOUT_REG (out), BQ25505_VBAT_OK (out)

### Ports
EH_nEN (in), PWR_MGMT (harness PWR_MGMT)

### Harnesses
PWR_MGMT: SSM_5V_EN, VBAT_OK, SSM_PWR_nEN

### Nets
GND: C70.2 C71.1 C72.2 C75.2 C76.2 C101.1 R45.1 R56.2 R90.1 R93.1 R122.2 R139.1 TP19.1 TP23.1 U10.3(VSS) U10.4(NC) U10.5(EN1) U10.12(VSS) U10.14(NC) U10.15(PAD) U12.3(GND) U22.2(GND)
ISense-: C70.1 C71.2 JP19.1 JP30.1 TP20.1 U10.1(IN) U10.6(EN2)  [also labelled VUSB_5V]
VCC_5V: C75.1 R54.2 TP22.1 U12.4(VOUT)
VCC_GPS: R96.1
VCC_MAIN: JP7.2 JP19.3 R91.2 R95.2 R96.2 U22.3(NC) U22.5(V+)
VCC_SSM: R95.1 TP1.1 U22.4(COM)
VCCIO_DAC: JP7.3
EH_nEN: Q7.A2(G2) Q7.C1(G1) R139.2 TP2.1 ; port EH_nEN
EH_VOUT_REG: Q7.C2(D1) R68.1 ; sheet U_PWR_EH/EH_VOUT_REG
ISense+: JP30.2 Q7.A1(D2) R68.2 TP21.1
SSM_5V_EN: R55.1 U12.6(EN) ; port PWR_MGMT.SSM_5V_EN  [project net PWR_MGMT.SSM_5V_EN]
SSM_PWR_nEN: R91.1 R93.2 U22.6(IN) ; port PWR_MGMT.SSM_PWR_nEN  [project net PWR_MGMT.SSM_PWR_nEN]
VBAT_OK: sheet U_PWR_EH/BQ25505_VBAT_OK, port PWR_MGMT.VBAT_OK  [project net BQ25505_VBAT_OK]
NetC72_1: C72.1 JP7.1 L5.2 TP18.1 U10.11(OUT)
NetC76_1: C76.1 C101.2 JP19.2 L6.1 R55.2 U12.1(VIN)
NetL5_1: L5.1 R46.1 U10.13(SW)
NetL6_2: L6.2 U12.5(L)
NetR45_2: R45.2 R46.2 U10.2(SW)
NetR54_1: R54.1 R56.1 U12.2(FB)
NetR88_1: R88.1 R89.2 U10.9(VOUT_SET)
NetR88_2: R88.2 U10.7(VRDIV)
NetR89_1: R89.1 R90.2 U10.8(VIN_OK_SET)
NetR122_1: R122.1 U22.1(NO)

Not connected (* = marked no-connect by the designer): Q7 B1(S)* B2(S)*; U10 10(VIN_OK)*

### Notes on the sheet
- TPS62736 Compatibility:
  · Mount R46 and do not mount R45 for TPS62737.
  · Mount R45 and do not mount R46 for TPS62736.
- VOUT = 3.017V
- VIN_OK = 3.117V
- Power Sensing

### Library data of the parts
C70 C72 = GRM188R61A226ME15D: CAP, CERM, 22 µF, 10 V, +/- 20%, X5R, 0603; Manufacturer: MuRata; Polarized: N; CompType: Capacitor; Value: 22uF; U/M: EA; Cap_F: 0.000022; Tolerance_%: 20; Value1: Unknown; VDC_V: 10; Value2: 10V; TaMin_C: -55; TaMax_C: 85; SizeArea_mm2: 1.28; SizeAreaWB_mm2: 4.68; SizeX_mm: 1.6; SizeY_mm: 0.8; SizeZ_mm: 1; AEC Category: Q200
C71 C101 = GRM155R70J104KA01D: CAP, CERM, 0.1 µF, 6.3 V, +/- 10%, X7R, 0402; Manufacturer: MuRata; Polarized: N; CompType: Capacitor; Value: 0.1uF; U/M: EA; Cap_F: 0.0000001; Tolerance_%: 10; Value1: Unknown; VDC_V: 6.3; Value2: 6.3V; TaMin_C: -55; TaMax_C: 125; SizeArea_mm2: 0.5; SizeAreaWB_mm2: 3; SizeX_mm: 1; SizeZ_mm: 0.6; AEC Category: Q200
C75 C76 = GRM188R60J106ME47D: as C113 on sheet TIDA-01452_Sensors
JP7 JP19 = TMM-103-01-T-S: Header, 2mm, 3x1, Tin, TH; Manufacturer: Samtec; SymbolCreator: a0799628; U/M: EA
JP30 = TMM-102-01-T-S: as JP1 on sheet TIDA-01452_I3Mote
L5 = LPS4018-103MLB: Inductor, Shielded Drum Core, Ferrite, 10 µH, 1.25 A, 0.2 ohm, SMD; Manufacturer: Coilcraft; Value: 10uH; Ind_H: 10.0E-6; Imax_A: 1.25; Irms: 1.25A @ 40C rise; Isat: 1.3A @ 30% inductance drop; DCR_ohm: 0.2; Value1: 0.2 ohm; Value2: 1.25A; AEC Category: Q200
L6 = EPL3015-472MLB: Inductor, Shielded, Ferrite, 4.7 µH, 1.2 A, 0.14 ohm, SMD; Manufacturer: Coilcraft; Value: 4.7uH; Ind_H: 4.7E-6; Imax_A: 1.2; Irms: 1.4A @ 40C rise; Isat: 1.2A @ 30% inductance drop; DCR_ohm: 0.14; Value2: 1.2A; AEC Category: Q200
Q7 = CSD75208W1015: MOSFET, P-CH, -20 V, -1.6 A,; Manufacturer: Texas Instruments; Alternate Manufacturer: None; SymbolCreator: Altium; U/M: EA; ChType: P; Value: -20V; Value1: 0.09 ohm; Rdson45_ohm: 0.09; Value2: 1.9 nC; QgTyp_nC: 1.9; Vgs_V: -6
R45 R46 R54 R56 R68 R95 R96 R122 = CRCW04020000Z0ED: as R31 on sheet TIDA-01452_I3Mote
R55 R91 R93 R139 = CRCW04021M00FKED: RES, 1.00 M, 1%, 0.063 W, 0402; Manufacturer: Vishay-Dale; CompType: Resistor; Value: 1.00Meg; Res_ohm: 1000000; Value_Code: 1M00; Tolerance_%: 1; Power_W: 0.063; Value2: 0.063W; VDC_V: 50; TempCo: 100 ppm/C; EIA_Code: E96; U/M: EA; AEC Category: Q200
R88 = CRCW04027M87FKED: RES, 7.87 M, 1%, 0.063 W, 0402; Manufacturer: Vishay-Dale; CompType: Resistor; Value: 7.87Meg; Res_ohm: 7870000; Value_Code: 7M87; Tolerance_%: 1; Power_W: 0.063; Value2: 0.063W; VDC_V: 50; TempCo: 100 ppm/C; EIA_Code: E96; U/M: EA; AEC Category: Q200
R89 = CRCW0402169KFKED: RES, 169 k, 1%, 0.063 W, 0402; Manufacturer: Vishay-Dale; CompType: Resistor; Value: 169k; Res_ohm: 169000; Tolerance_%: 1; Power_W: 0.063; Value2: 0.063W; VDC_V: 50; TempCo: 100 ppm/C; EIA_Code: E96; U/M: EA; AEC Category: Q200
R90 = CRCW04025M11FKED: RES, 5.11 M, 1%, 0.063 W, 0402; Manufacturer: Vishay-Dale; CompType: Resistor; Value: 5.11Meg; Res_ohm: 5110000; Value_Code: 5M11; Tolerance_%: 1; Power_W: 0.063; Value2: 0.063W; VDC_V: 50; TempCo: 100 ppm/C; EIA_Code: E96; U/M: EA; AEC Category: Q200
TP1 TP2 TP18-TP23 = TEST_POINT_ROUND_1.2: Round Test Point, 1.2mm diam.
U10 = TPS62737RGYR: Programmable Output Voltage Ultra-Low Power Buck Converter with up to 50mA / 200 mA Output Current, RGY0014A; Alternate PartNumber: TPS62737RGYT; Manufacturer: Texas Instruments; SymbolCreator: a0411947; SizeArea_mm2: 12.25; SizeX_mm: 3.5; SizeZ_mm: 1; CompType: IC; U/M: EA
U12 = TPS61222DCKR: LOW INPUT VOLTAGE STEP-UP CONVERTER IN 6 PIN SC-70 PACKAGE, DCK0006A; Alternate PartNumber: TPS61222DCKT; Manufacturer: Texas Instruments; SymbolCreator: a0799628; SizeArea_mm2: 4.2; SizeX_mm: 2.1; SizeY_mm: 2; SizeZ_mm: 1.1; CompType: IC; U/M: EA
U22 = TS5A3160DBVR: 1-Ohm SPDT ANALOG SWITCH 5-V/3.3-V SINGLE-CHANNEL 2:1 MULTIPLEXER/DEMULTIPLEXER, DBV0006A; Alternate PartNumber: TS5A3160DBVT; Manufacturer: Texas Instruments; SymbolCreator: Altium; SizeArea_mm2: 8.12; SizeX_mm: 2.8; SizeY_mm: 2.9; SizeZ_mm: 1.45; CompType: IC; U/M: EA

## Sheet TIDA-01452_PWR_EH.SchDoc: PWR_EH
size 431 x 279 mm; Date: Not shown in title block; ApprovedBy: Not shown in title block; CheckedBy: Not shown in title block; Author: Not shown in title block; CompanyName: Not shown in title block; DrawnBy: Il Han Kim; Engineer: Not shown in title block; Organization: Not shown in title block; Address1: Not shown in title block; Address2: Not shown in title block; Address3: Not shown in title block; Address4: Not shown in title block; DocumentNumber: 9; Revision: Use project parameter SCH_Rev; SheetNumber: 10; SheetTotal: 12; PageSetup: Record=PageOptions¦CenterHorizontal=True¦CenterVertical=True¦PrintScale=1.00¦XCorrection=1.00¦YCorrection=1.00¦PrintKind=0¦BorderSize=5000000¦LeftOffset=0¦BottomOffset=0¦Orientation=2¦PaperLength=1000¦PaperWidth=1000¦Scale=100¦PaperSource=15¦PrintQuality=600¦MediaType=1¦DitherType=10¦PaperKind=Letter¦PrintScaleMode=1
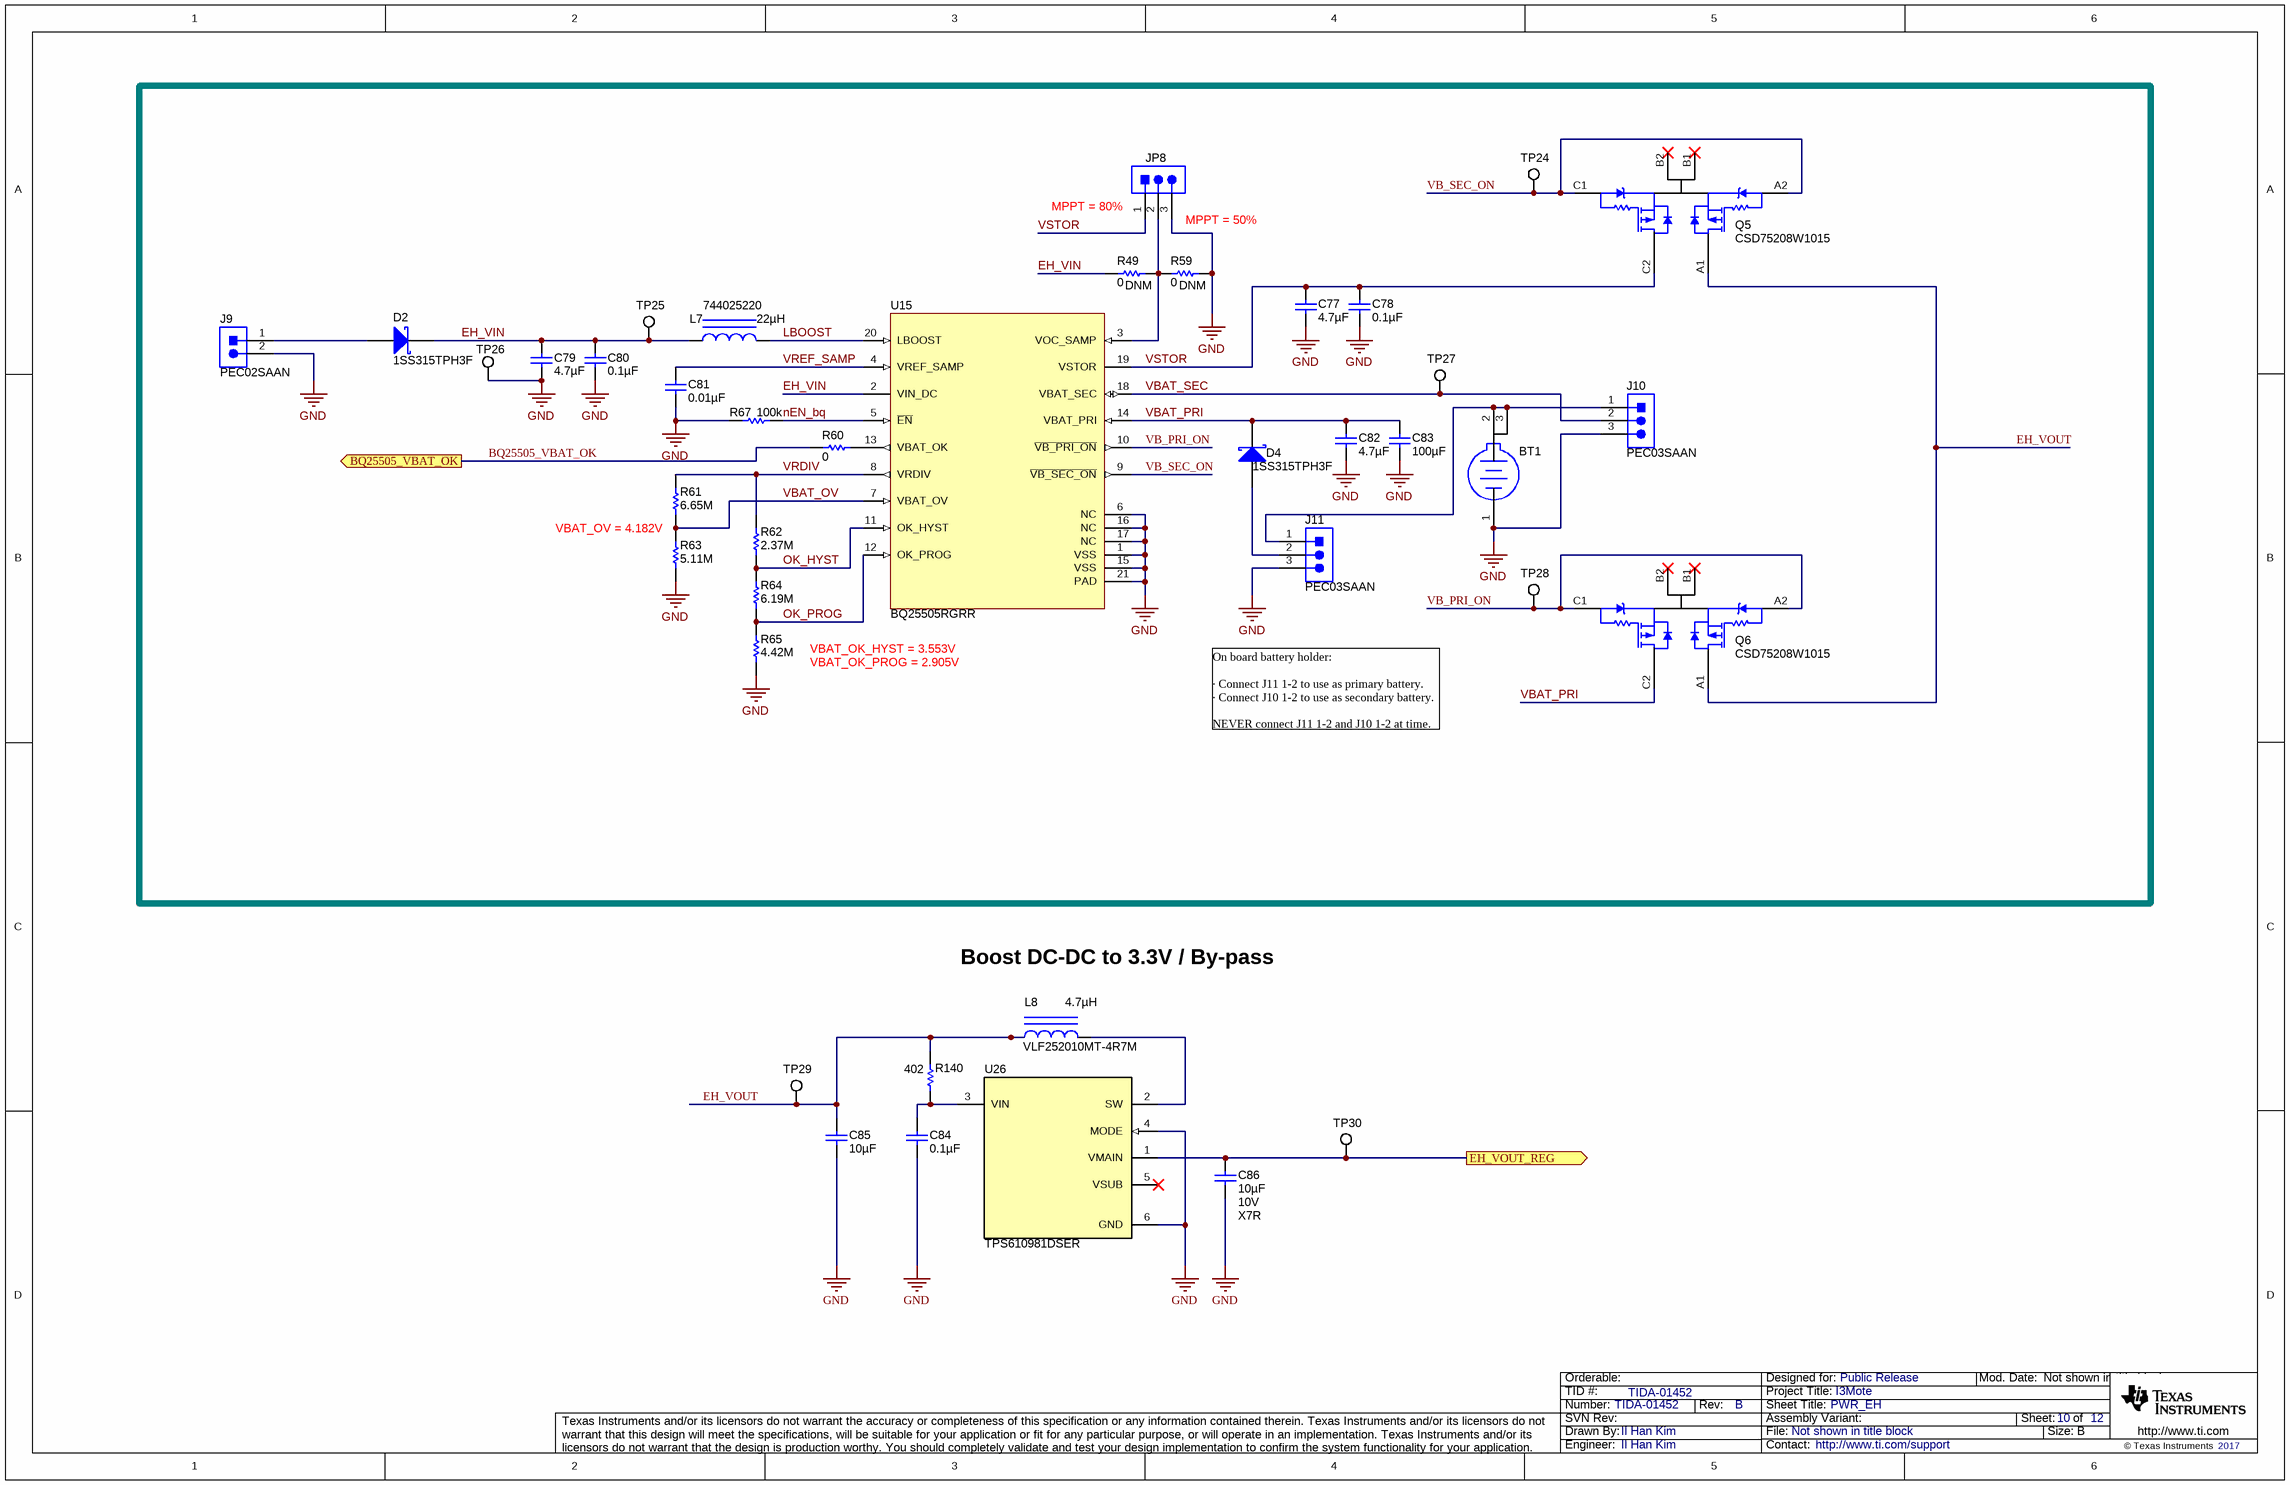
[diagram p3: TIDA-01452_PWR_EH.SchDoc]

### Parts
BT1  BAT-HLD-001  [LINX_BAT-HLD-001]  (value not drawn)
C77  ValueDisplayed: 4.7µF  [0402]  (hidden comment: C1005X5R1A475K050BC)
C78  ValueDisplayed: 0.1µF  [0402]  (hidden comment: GRM155R70J104KA01D)
C79  ValueDisplayed: 4.7µF  [0402]  (hidden comment: C1005X5R1A475K050BC)
C80  ValueDisplayed: 0.1µF  [0402]  (hidden comment: GRM155R70J104KA01D)
C81  ValueDisplayed: 0.01µF  [0402]  (hidden comment: C0402C103J5RACTU)
C82  ValueDisplayed: 4.7µF  [0402]  (hidden comment: C1005X5R1A475K050BC)
C83  ValueDisplayed: 100µF  [1206_190]  (hidden comment: C3216X5R1A107M160AC)
C84  ValueDisplayed: 0.1µF  [0402]  (hidden comment: GCM155R71H104KE02D)
C85  ValueDisplayed: 10µF  [0603]  (hidden comment: GRM188R60J106ME47D)
C86  ValueDisplayed: 10µF  Value2: 10V  TempCo: X7R  [0805_HV]  (hidden comment: GRM21BR71A106KE51L)
D2  1SS315TPH3F  [sod-323]
D4  1SS315TPH3F  [sod-323]
J9  PEC02SAAN  [CONN_PEC02SAAN]
J10  PEC03SAAN  [CONN_PEC03SAAN]
J11  PEC03SAAN  [CONN_PEC03SAAN]
JP8  TMM-103-01-T-S  [CONN_TMM-103-01-T-S]  (value not drawn)
L7  744025220  ValueDisplayed: 22µH  [WE-TPC_2828]
L8  VLF252010MT-4R7M  ValueDisplayed: 4.7µH  [IND_VLF252010]
Q5  CSD75208W1015  [YZC0006ABBB]
Q6  CSD75208W1015  [YZC0006ABBB]
R49  DNM  ValueDisplayed: 0  [0402]
R59  DNM  ValueDisplayed: 0  [0402]
R60  ValueDisplayed: 0  [0402]  (hidden comment: CRCW04020000Z0ED)
R61  ValueDisplayed: 6.65M  [0402]  (hidden comment: CRCW04026M65FKED)
R62  ValueDisplayed: 2.37M  [0402]  (hidden comment: CRCW04022M37FKED)
R63  ValueDisplayed: 5.11M  [0402]  (hidden comment: CRCW04025M11FKED)
R64  ValueDisplayed: 6.19M  [0402]  (hidden comment: CRCW04026M19FKED)
R65  ValueDisplayed: 4.42M  [0402]  (hidden comment: CRCW04024M42FKED)
R67  ValueDisplayed: 100k  [0402]  (hidden comment: CRCW0402100KFKED)
R140  ValueDisplayed: 402  [0402]  (hidden comment: CRCW0402402RFKED)
TP24  NA  [TPS0.8]  (value not drawn)  (no BOM)
TP25  NA  [TPS0.8]  (value not drawn)  (no BOM)
TP26  NA  [TPS0.8]  (value not drawn)  (no BOM)
TP27  NA  [TPS0.8]  (value not drawn)  (no BOM)
TP28  NA  [TPS0.8]  (value not drawn)  (no BOM)
TP29  NA  [TPS0.8]  (value not drawn)  (no BOM)
TP30  NA  [TPS0.8]  (value not drawn)  (no BOM)
U15  BQ25505RGRR  [RGR0020A]
U26  TPS610981DSER  [DSE0006A]

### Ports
BQ25505_VBAT_OK (out), EH_VOUT_REG (out)

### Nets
GND: BT1.1(-) C77.2 C78.2 C79.2 C80.2 C81.2 C82.2 C83.2 C84.2 C85.2 C86.1 J9.2 J10.3 J11.3 JP8.3 R59.2 R63.1 R65.1 R67.2 TP26.1 U15.1(VSS) U15.6(NC) U15.15(VSS) U15.16(NC) U15.17(NC) U15.21(PAD) U26.4(MODE) U26.6(GND)
BQ25505_VBAT_OK: R60.1 ; port BQ25505_VBAT_OK
EH_VIN: C79.1 C80.1 D2.1(K) L7.1 R49.1 TP25.1 U15.2(VIN_DC)
EH_VOUT: C85.1 L8.1 Q5.A1(D2) Q6.A1(D2) R140.2 TP29.1
EH_VOUT_REG: C86.2 TP30.1 U26.1(VMAIN) ; port EH_VOUT_REG
LBOOST: L7.2 U15.20(LBOOST)
nEN_bq: R67.1 U15.5(~{EN})
OK_HYST: R62.1 R64.2 U15.11(OK_HYST)
OK_PROG: R64.1 R65.2 U15.12(OK_PROG)
VB_PRI_ON: Q6.A2(G2) Q6.C1(G1) TP28.1 U15.10(~{VB_PRI_ON})
VB_SEC_ON: Q5.A2(G2) Q5.C1(G1) TP24.1 U15.9(~{VB_SEC_ON})
VBAT_OV: R61.1 R63.2 U15.7(VBAT_OV)
VBAT_PRI: C82.1 C83.1 D4.1(K) Q6.C2(D1) U15.14(VBAT_PRI)
VBAT_SEC: J10.2 TP27.1 U15.18(VBAT_SEC)
VRDIV: R61.2 R62.2 U15.8(VRDIV)
VREF_SAMP: C81.1 U15.4(VREF_SAMP)
VSTOR: C77.1 C78.1 JP8.1 Q5.C2(D1) U15.19(VSTOR)
NetBT1_2: BT1.2(+) BT1.3(+) J10.1 J11.1
NetC84_1: C84.1 R140.1 U26.3(VIN)
NetD2_2: D2.2(A) J9.1
NetD4_2: D4.2(A) J11.2
NetJP8_2: JP8.2 R49.2 R59.1 U15.3(VOC_SAMP)
NetL8_2: L8.2 U26.2(SW)
NetR60_2: R60.2 U15.13(VBAT_OK)

Not connected (* = marked no-connect by the designer): Q5 B1(S)* B2(S)*; Q6 B1(S)* B2(S)*; U26 5(VSUB)*

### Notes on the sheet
- (near JP8) MPPT = 80%
- (near JP8) MPPT = 50%
- VBAT_OV = 4.182V
- VBAT_OK_HYST = 3.553V
- VBAT_OK_PROG = 2.905V
- On board battery holder:
  · Connect J11 1-2 to use as primary battery.
  · Connect J10 1-2 to use as secondary battery.
  NEVER connect J11 1-2 and J10 1-2 at time.
- Boost DC-DC to 3.3V / By-pass

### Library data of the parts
BT1 = BAT-HLD-001: Battery Holder, Retainer clip, SMT; Manufacturer: Linx Technologies; SymbolCreator: a0411947
C77 C79 C82 = C1005X5R1A475K050BC: CAP, CERM, 4.7 µF, 10 V, +/- 10%, X5R, 0402; Manufacturer: TDK; Polarized: N; CompType: Capacitor; Value: 4.7uF; U/M: EA; Cap_F: 0.0000047; Tolerance_%: 10; Value1: Unknown; Value2: 10V; TaMin_C: -55; TaMax_C: 85; AEC Category: Q200
C78 C80 = GRM155R70J104KA01D: CAP, CERM, 0.1 µF, 6.3 V, +/- 10%, X7R, 0402; Manufacturer: MuRata; Polarized: N; CompType: Capacitor; Value: 0.1uF; U/M: EA; Cap_F: 0.0000001; Tolerance_%: 10; Value1: Unknown; VDC_V: 6.3; Value2: 6.3V; TaMin_C: -55; TaMax_C: 125
C81 = C0402C103J5RACTU: CAP, CERM, 0.01 µF, 50 V, +/- 5%, X7R, 0402; Manufacturer: Kemet; Polarized: N; CompType: Capacitor; Value: 0.01uF; U/M: EA; Cap_F: 0.00000001; Tolerance_%: 5; Value1: Unknown; VDC_V: 50; Value2: 50V; TaMin_C: -55; TaMax_C: 125; AEC Category: Q200
C83 = C3216X5R1A107M160AC: CAP, CERM, 100 µF, 10 V, +/- 20%, X5R, 1206_190; Manufacturer: TDK; Polarized: N; CompType: Capacitor; Value: 100uF; U/M: EA; Cap_F: 0.0001; Tolerance_%: 20; Value1: Unknown; VDC_V: 10; Value2: 10V; TaMin_C: -55; TaMax_C: 85; Cap_Case: 1206
C84 = GCM155R71H104KE02D: as C47 on sheet TIDA-01452_Sensors
C85 = GRM188R60J106ME47D: as C113 on sheet TIDA-01452_Sensors
C86 = GRM21BR71A106KE51L: CAP, CERM, 10 µF, 10 V, +/- 10%, X7R, 0805; Manufacturer: MuRata; Polarized: N; CompType: Capacitor; Value: 10uF; U/M: EA; Cap_F: 0.00001; Tolerance_%: 10; ESR_ohm: 0.003; Value1: 0.003 ohm; TaMin_C: -55; TaMax_C: 125; Cap_Case: 0805
D2 D4 = 1SS315TPH3F: Diode, Schottky, 5V, 0.03A, SOD-323; Manufacturer: Toshiba; U/M: EA; Vf_V: 0.38; Value2: 0.38V; Io_A: 0.03; Vr_V: 5; TJmax_C: 125
J9 = PEC02SAAN: Header, 100mil, 2x1, Tin, TH; Manufacturer: Sullins Connector Solutions; SymbolCreator: a0412235; U/M: EA
J10 J11 = PEC03SAAN: Header, 100mil, 3x1, Tin, TH; Manufacturer: Sullins Connector Solutions; SymbolCreator: a0799628; Pitch_mm: 2.54; Gender: Male; Shrouded: N; Row_Count: 1; Current_A: 3; Voltage_V: 1800; Cert_UL: Y
JP8 = TMM-103-01-T-S: as JP7 on sheet TIDA-01452_PowerManagement
L7 = 744025220: Inductor, Shielded Drum Core, Ferrite, 22uH, 0.5A, 0.525 ohm, SMD; Manufacturer: Wurth Elektronik eiSos; Ind_H: 22.0E-6; Imax_A: 0.5; Irms: 0.5A @ 40C rise; Isat: 0.75A @ 35% inductance drop; DCR_ohm: 0.525; U/M: EA
L8 = VLF252010MT-4R7M: Inductor, Shielded, Ferrite, 4.7uH, 0.64A, 0.25 ohm, SMD; Manufacturer: TDK; Ind_H: 4.7E-6; Imax_A: 0.64; Irms: 0.95A @ 40C rise; Isat: 0.64A @ 30% inductance drop; DCR_ohm: 0.25; U/M: EA
Q5 Q6 = CSD75208W1015: as Q7 on sheet TIDA-01452_PowerManagement
R49 R59 = CRCW04020000Z0ED: as R118 on sheet TIDA-01452_Sensors
R60 = CRCW04020000Z0ED: as R31 on sheet TIDA-01452_I3Mote
R61 = CRCW04026M65FKED: RES, 6.65 M, 1%, 0.063 W, 0402; Manufacturer: Vishay-Dale; CompType: Resistor; Value: 6.65Meg; Res_ohm: 6650000; Value_Code: 6M65; Tolerance_%: 1; Power_W: 0.063; Value2: 0.063W; VDC_V: 50; TempCo: 100 ppm/C; EIA_Code: E96; U/M: EA; AEC Category: Q200
R62 = CRCW04022M37FKED: RES, 2.37 M, 1%, 0.063 W, 0402; Manufacturer: Vishay-Dale; CompType: Resistor; Value: 2.37Meg; Res_ohm: 2370000; Value_Code: 2M37; Tolerance_%: 1; Power_W: 0.063; Value2: 0.063W; VDC_V: 50; TempCo: 100 ppm/C; EIA_Code: E96; U/M: EA; AEC Category: Q200
R63 = CRCW04025M11FKED: as R90 on sheet TIDA-01452_PowerManagement
R64 = CRCW04026M19FKED: RES, 6.19 M, 1%, 0.063 W, 0402; Manufacturer: Vishay-Dale; CompType: Resistor; Value: 6.19Meg; Res_ohm: 6190000; Value_Code: 6M19; Tolerance_%: 1; Power_W: 0.063; Value2: 0.063W; VDC_V: 50; TempCo: 100 ppm/C; EIA_Code: E96; U/M: EA; AEC Category: Q200
R65 = CRCW04024M42FKED: RES, 4.42 M, 1%, 0.063 W, 0402; Manufacturer: Vishay-Dale; CompType: Resistor; Value: 4.42Meg; Res_ohm: 4420000; Value_Code: 4M42; Tolerance_%: 1; Power_W: 0.063; Value2: 0.063W; VDC_V: 50; TempCo: 100 ppm/C; EIA_Code: E96; U/M: EA; AEC Category: Q200
R67 = CRCW0402100KFKED: RES, 100 k, 1%, 0.063 W, 0402; Manufacturer: Vishay-Dale; CompType: Resistor; Value: 100k; Res_ohm: 100000; Tolerance_%: 1; Power_W: 0.063; Value2: 0.063W; VDC_V: 50; TempCo: 100 ppm/C; EIA_Code: E96; U/M: EA; AEC Category: Q200
R140 = CRCW0402402RFKED: RES, 402, 1%, 0.063 W, 0402; Manufacturer: Vishay-Dale; CompType: Resistor; Value: 402; Value_Code: 402R; Tolerance_%: 1; Power_W: 0.063; Value2: 0.063W; VDC_V: 50; TempCo: 100 ppm/C; EIA_Code: E96; U/M: EA; AEC Category: Q200
TP24-TP30 = TEST_POINT_ROUND_1.2: Round Test Point, 1.2mm diam.
U15 = BQ25505RGRR: Ultra Low Power Boost Converter with Battery Management for Energy Harvester Applications, RGR0020A; Alternate PartNumber: BQ25505RGRT; Manufacturer: Texas Instruments; SymbolCreator: a0412235; CompType: IC; U/M: EA
U26 = TPS610981DSER: Ultra-Low Quiescent Current Synchronous Boost with Integrated LDO/Load Switch, DSE0006A; Alternate PartNumber: TPS610981DSET; Manufacturer: Texas Instruments; SymbolCreator: Altium; SizeArea_mm2: 2.25; SizeAreaWB_mm2: 6.25; SizeX_mm: 1.5; SizeZ_mm: 0.8; CompType: IC; U/M: EA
